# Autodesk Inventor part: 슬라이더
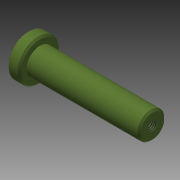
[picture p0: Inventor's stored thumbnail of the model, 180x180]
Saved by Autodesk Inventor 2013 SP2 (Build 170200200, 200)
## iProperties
Created: 2011-04
Part Number: 슬라이더
Document SubType Name: Modeling
Density: 1 g/cm^3
Material: 일반
Author: pww
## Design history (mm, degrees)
sketch "스케치1"
  geometry: L1 (-7, 0)-(63, 0); L2 (63, 0)-(63, 7.5); L3 (63, 7.5)-(0, 7.5); L4 (-7, 0)-(-7, 11.5); L5 (-7, 11.5)-(0, 11.5); L6 (0, 11.5)-(0, 7.5); 1 further point
  constraints: 12 end point, 3 perpendicular, 2 horizontal, 2 point on line, 1 parallel
  dimensions: "d1" = 70 distance of L1.start L1.end; "d19" = 15 diameter of L3 L1; "d20" = 7 distance of L4.end L5.end; "d21" = 23 diameter of L5 L1
revolve "회전1" stored, may be unused: angle "d4" = 90 deg
chamfer "모따기1" distance "d16" = 1; stored, may be unused: second distance "d17" = 2, angle "d18" = 45 deg
hole "구멍2" diameter "d24" = 4.917; stored, may be unused: countersink angle "d28" = 90 deg, drill point angle "d30" = 118 deg; dims "d22" = 10, "d23" = 10, "d25" = 10, "d26" = 4, "d27" = 2, "d29" = 13
node "솔리드1"
